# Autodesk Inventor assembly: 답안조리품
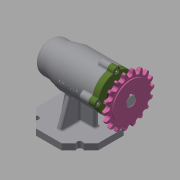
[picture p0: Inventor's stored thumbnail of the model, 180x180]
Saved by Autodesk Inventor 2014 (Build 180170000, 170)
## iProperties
Created: 2021-01
Part Number: 답안조리품
Document SubType Name: Assembly
Designer: kh
Author: kh
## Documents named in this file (12)
- C:\Users\kh\Desktop\710106V1016\답안조리품.iam
- C:\Users\kh\Desktop\710106V1016\본체.ipt
- C:\Users\kh\Desktop\710106V1016\멈춤나사 M3.ipt
- C:\Users\kh\Desktop\710106V1016\베어링 6004.ipt
- C:\Users\kh\Desktop\710106V1016\베어링 51202.ipt
- C:\Users\kh\Desktop\710106V1016\볼트 M4.ipt
- C:\Users\kh\Desktop\710106V1016\스프로킷.ipt
- C:\Users\kh\Desktop\710106V1016\어댑터슬리브.ipt
- C:\Users\kh\Desktop\710106V1016\오일 실.ipt
- C:\Users\kh\Desktop\710106V1016\축.ipt
- C:\Users\kh\Desktop\710106V1016\커버.ipt
- C:\Users\kh\Desktop\710106V1016\키 5 x 5 x 14.ipt
